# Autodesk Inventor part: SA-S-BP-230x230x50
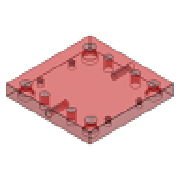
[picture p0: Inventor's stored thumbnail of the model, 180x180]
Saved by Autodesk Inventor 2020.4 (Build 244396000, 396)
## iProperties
Created: 2019-01
Part Number: SA-S-BP-230x230x50
Material: S 55 C
Description: Core Plate
Document SubType Name: Modeling
Designer: mel
Standard Revision: 1
Manufacturer: FUTABA
Language: fr-FR
Size Designation: 230x230x50
Categories: <MemberInstance><Categories><Category DisplayName="Moule" InternalName="349578f2-f4d4-4954-8c09-8e99297a61c0" Mnemonic="MOLD"><Category DisplayName="Plaque de m
Density: 7.85 g/cm^3
Appearance: Dark Red
IsCustomPart: 1
Author: mel
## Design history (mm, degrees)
sketch "Sketch1"
  geometry: L1 (-115, 115)-(115, 115); L2 (115, 115)-(115, -115); L3 (115, -115)-(-115, -115); L4 (-115, -115)-(-115, 115); 7 further points
  constraints: 8 end point, 2 horizontal alignment, 2 midpoint, 2 parallel, 1 horizontal, 1 perpendicular, 1 vertical alignment
  dimensions: "d123" = 230 distance between parallel lines of L2 L4 (= W_); "d124" = 230 distance between parallel lines of L3 L1 (= L); "d125" = 90 vertical distance of point (0, 0) point (-53, 90) (= 0.5 x RP_L); "d126" = 53 horizontal distance of point (0, 0) point (-53, 90) (= 0.5 x RP_W); "d127" = 92 horizontal distance of point (0, 0) point (-92, 92) (= 0.5 x GP_W); "d128" = 92 horizontal distance of point (0, 0) point (-92, 92) (= 0.5 x GP_L); "d129" = 92.5 horizontal distance of point (0, 0) point (-92.5, 53) (= 0.5 x S1_W); "d130" = 53 vertical distance of point (0, 0) point (-92.5, 53) (= 0.5 x S1_L); "d140" = 92 horizontal distance of point (92, 92) point (0, 0) (= 0.5 x GP_W)
extrude "Extrusion1" new body sketch "Sketch1" distance "d20" = 50 (= H_); taper "d30" = 0 deg
sketch "Sketch2"
  geometry: L1 (230, 0)-(0, 0) reference; 3 further points
  constraints: 1 midpoint, 1 vertical alignment
  dimensions: "d186" = 25 distance from line of L1 point (115, 25) (= 0.5 x H_)
hole "Hole1" sketch "Sketch2" at (115, 25) diameter "d104" = 13.835; stored, may be unused: countersink angle "d108" = 90 deg, drill point angle "d110" = 118 deg; dims "d105" = 29 (= le), "d106" = 26 (= GP_d2), "d107" = 6 (= GP_k), "d109" = 39 (= ke)
sketch "Sketch3"
  geometry: L1 (0, 0)-(230, 0) reference; 3 further points
  constraints: 1 midpoint, 1 vertical alignment
  dimensions: "d187" = 25 distance from line of point (115, -25) L1 (= 0.5 x H_)
hole "Hole2" sketch "Sketch3" at (115, -25) diameter "d113" = 13.835; stored, may be unused: countersink angle "d117" = 90 deg, drill point angle "d119" = 118 deg; dims "d114" = 29 (= le), "d115" = 26 (= GP_d2), "d116" = 6 (= GP_k), "d118" = 39 (= ke)
hole "Hole3" sketch "Sketch1" diameter "d131" = 10.106; stored, may be unused: countersink angle "d135" = 90 deg, drill point angle "d137" = 118 deg; dims "d132" = 15 (= H_l), "d133" = 4, "d134" = 2, "d136" = 24 (= H_u)
pattern_linear "Rectangular Pattern1" dims "d164" = 106 (computed from S1_L, Ns), "d167" = 185 (computed from S1_W, Nw)
hole "Hole4" sketch "Sketch1" diameter "d141" = 20 (= GP_d1); stored, may be unused: countersink angle "d145" = 90 deg, drill point angle "d147" = 0 deg; dims "d142" = 6, "d143" = 26 (= GP_d2), "d144" = 6 (= GP_k), "d146" = 50 (= H_)
pattern_linear "Rectangular Pattern2" dims "d170" = 184 (computed from GP_L, Nl)
hole "Hole5" sketch "Sketch1" diameter "d148" = 20 (= GP_d1); stored, may be unused: countersink angle "d152" = 90 deg, drill point angle "d154" = 0 deg; dims "d149" = 6, "d150" = 26 (= GP_d2), "d151" = 6 (= GP_k), "d153" = 50 (= H_)
pattern_linear "Rectangular Pattern3" dims "d173" = 182 (computed from GP_L2, GP_L1, Nl)
hole "Hole6" sketch "Sketch1" diameter "d155" = 15 (= RP_dt); stored, may be unused: countersink angle "d159" = 90 deg, drill point angle "d161" = 0 deg; dims "d156" = 6, "d157" = 26 (= GP_d2), "d158" = 6 (= GP_k), "d160" = 50 (= H_)
pattern_linear "Rectangular Pattern4" dims "d176" = 180 (computed from RP_L, Nl), "d179" = 106 (computed from RP_W, Nw)
chamfer "Chamfer1" distance "d180" = 0.5; stored, may be unused: second distance "d181" = 2, angle "d182" = 45 deg
body "Solid1"
other parameters: "L" = 230 [user parameter; used in 1 equation term], "W_" = 230 [user parameter; used in 3 equation terms], "H_" = 50 [user parameter; used in 8 equation terms], "GP_W" = 184 [user parameter; used in 2 equation terms], "GP_d1" = 20 [user parameter; used in 2 equation terms], "GP_d2" = 26 [user parameter; used in 5 equation terms], "GP_k" = 6 [user parameter; used in 5 equation terms], "S1_L" = 106 [user parameter; used in 2 equation terms], "S1_W" = 185 [user parameter; used in 2 equation terms], "GP_L1" = 92 [user parameter; used in 1 equation term], "RP_W" = 106 [user parameter; used in 2 equation terms], "RP_dt" = 15 [user parameter; used in 1 equation term], "GP_L" = 184 [user parameter; used in 2 equation terms], "d102" = 25 (= 0.5 x H_), "d103" = 115 (= 0.5 x W_), "d111" = 115 (= 0.5 x W_), "d112" = 25 (= 0.5 x H_), "le" = 29 [user parameter; used in 2 equation terms], "ke" = 39 [user parameter; used in 2 equation terms], "H_l" = 15 [user parameter; used in 1 equation term], "H_u" = 24 [user parameter; used in 1 equation term]
